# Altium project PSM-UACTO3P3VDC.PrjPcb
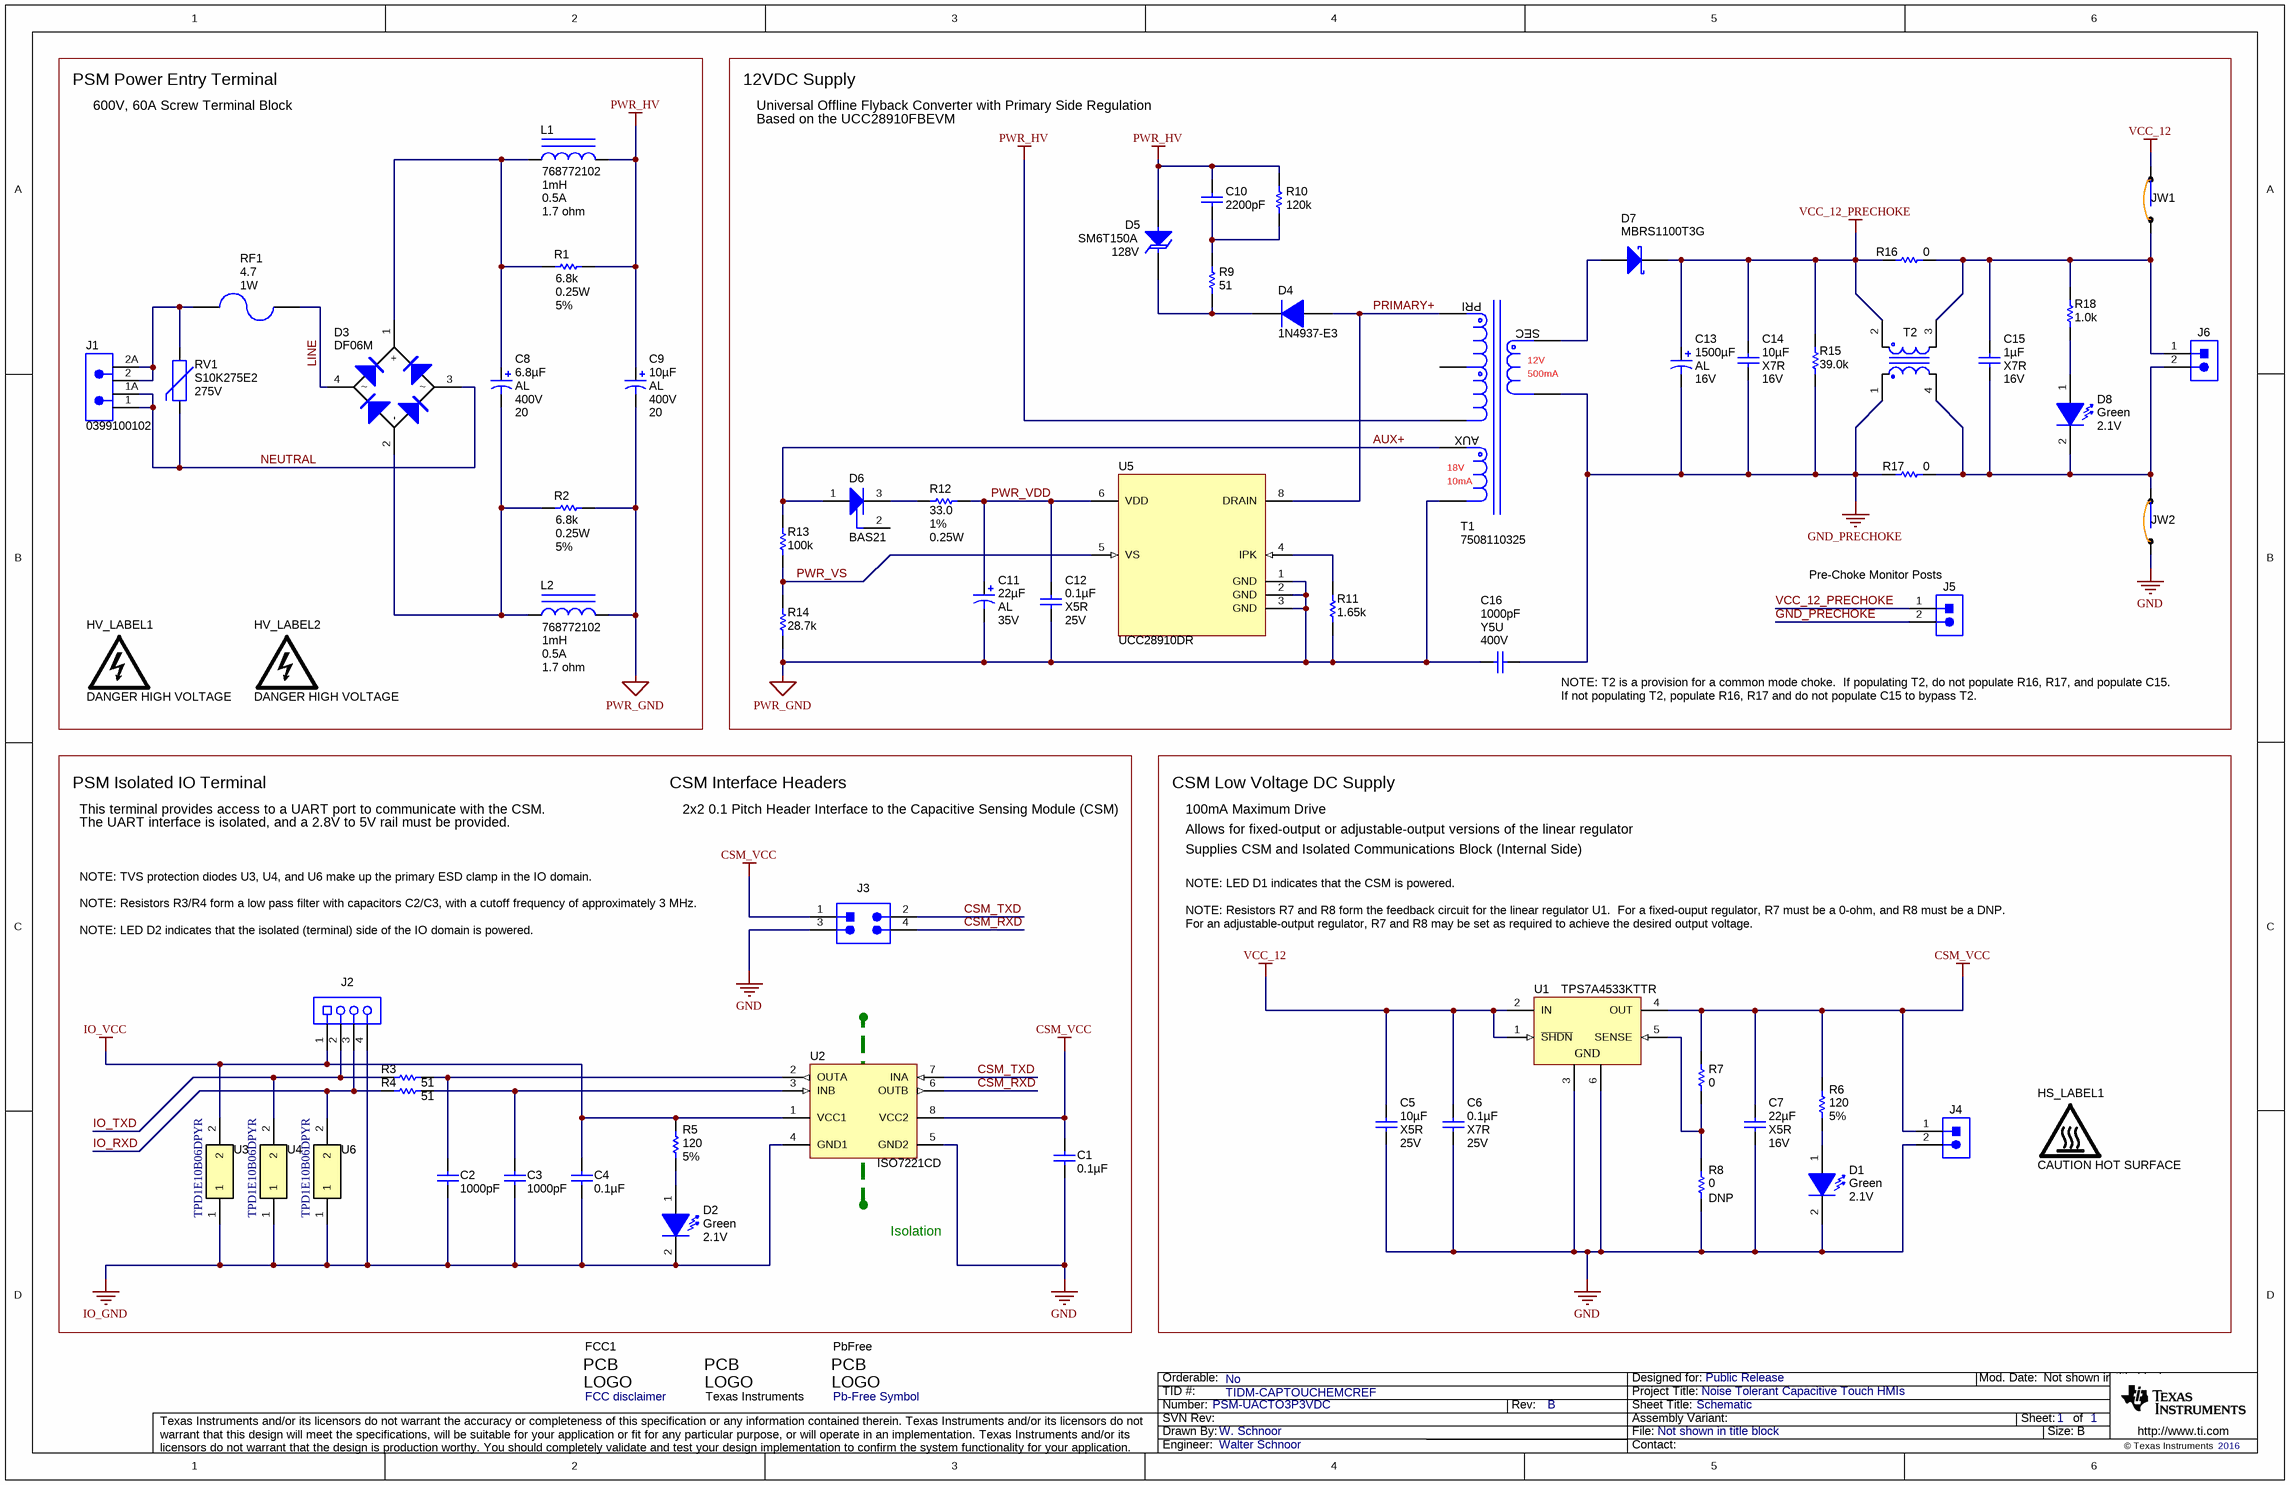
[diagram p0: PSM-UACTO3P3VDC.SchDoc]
CopyrightYear: 2016; EVM_Orderable: No; PCB_Layout: Walter Schnoor; PCB_Rev: B; PRJ_Customer: Public Release; PRJ_Engineer: Walter Schnoor; PRJ_Number: PSM-UACTO3P3VDC; PRJ_Title: Noise Tolerant Capacitive Touch HMIs; SCH_Rev: B; TID: TIDM-CAPTOUCHEMCREF
1 sheet, 68 parts. Net scope: global (net labels, ports and power ports of the same name join across sheets).
Board file: PSM-UACTO3P3VDC.PcbDoc

## Sheet PSM-UACTO3P3VDC.SchDoc: Schematic
size 431 x 279 mm; Date: Not shown in title block; ApprovedBy: Not shown in title block; CheckedBy: Not shown in title block; Author: Not shown in title block; CompanyName: Not shown in title block; DrawnBy: W. Schnoor; Engineer: Not shown in title block; Organization: Not shown in title block; Address1: Not shown in title block; Address2: Not shown in title block; Address3: Not shown in title block; Address4: Not shown in title block; DocumentNumber: 1; Revision: Use project parameter SCH_Rev; SheetNumber: 1; SheetTotal: 1; PageSetup: Record=PageOptions¦CenterHorizontal=True¦CenterVertical=True¦PrintScale=0.62¦XCorrection=1.00¦YCorrection=1.00¦PrintKind=0¦BorderSize=5000000¦LeftOffset=0¦BottomOffset=0¦Orientation=2¦PaperLength=2794¦PaperWidth=2159¦Scale=100¦PaperSource=15¦PrintQuality=600¦MediaType=1¦DitherType=10¦PrintScaleMode=1¦PaperKind=Letter (8.5 x 11")¦PaperIndex=1

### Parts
C1  ValueDisplayed: 0.1µF  [0603]  (hidden comment: GRM188R71C104KA01D)
C2  ValueDisplayed: 1000pF  [0603]  (hidden comment: 06031C102JAT2A)
C3  ValueDisplayed: 1000pF  [0603]  (hidden comment: 06031C102JAT2A)
C4  ValueDisplayed: 0.1µF  [0603]  (hidden comment: GRM188R71C104KA01D)
C5  ValueDisplayed: 10µF  Value2: 25V  TempCo: X5R  [0805_HV]  (hidden comment: C2012X5R1E106K125AB)
C6  ValueDisplayed: 0.1µF  Value2: 25V  TempCo: X7R  [0805_HV]  (hidden comment: 08053C104KAT2A)
C7  ValueDisplayed: 22µF  Value2: 16V  TempCo: X5R  [0805_HV]  (hidden comment: C2012X5R1C226K125AC)
C8  ValueDisplayed: 6.8µF  Tolerance_%: 20  Value2: 400V  Technology: AL  [CAPPR5-10x16]  (hidden comment: UCA2G6R8MPD1TD)
C9  ValueDisplayed: 10µF  Tolerance_%: 20  Value2: 400V  Technology: AL  [CAPPR5-10X20]  (hidden comment: EEUED2G100)
C10  ValueDisplayed: 2200pF  [1206]  (hidden comment: C3216C0G2J222J)
C11  ValueDisplayed: 22µF  Value2: 35V  Technology: AL  [M_500x1100]  (hidden comment: ECA-1VM220)
C12  ValueDisplayed: 0.1µF  Value2: 25V  TempCo: X5R  [0603]  (hidden comment: 06033D104KAT2A)
C13  ValueDisplayed: 1500µF  Value2: 16V  Technology: AL  [ZLJ_1000X2000]  (hidden comment: 16ZLJ1500M10X20)
C14  ValueDisplayed: 10µF  Value2: 16V  TempCo: X7R  [1206]  (hidden comment: C3216X7R1C106M)
C15  ValueDisplayed: 1µF  Value2: 16V  TempCo: X7R  [1206]  (hidden comment: C3216X7R1C105K/0.85)
C16  ValueDisplayed: 1000pF  Value2: 400V  TempCo: Y5U  [440L_930x1250]  (hidden comment: 440LD10-R)
D1  value Green  Value2: 2.1V  [HLMP-351_GREEN]  (hidden comment: HLMP-3519)
D2  value Green  Value2: 2.1V  [HLMP-351_GREEN]  (hidden comment: HLMP-3519)
D3  DF06M  [DIOB_DFM]
D4  1N4937-E3  [DO-41]
D5  SM6T150A  value 128V  [SMB]
D6  BAS21  [INF-SOT23_N]
D7  MBRS1100T3G  [SMB]
D8  value Green  Value2: 2.1V  [HLMP-351_GREEN]  (hidden comment: HLMP-3519)
FCC1  FCC disclaimer  [FCC_disclaimer]  (no BOM)
HS_LABEL1  CAUTION HOT SURFACE  [IEC_HotSurface_Small]  (no BOM)
HV_LABEL1  DANGER HIGH VOLTAGE  [IEC_HighVoltage_Medium]  (no BOM)
HV_LABEL2  DANGER HIGH VOLTAGE  [IEC_HighVoltage_Medium]  (no BOM)
J1  0399100102  [CONN_399100102]
J2  39544-3004  [MOLEX_39544-3004]  (value not drawn)
J3  PEC02DAAN  [Sullins_PEC02DAAN]  (value not drawn)
J4  HTSW-102-07-G-S  [Samtec_HTSW-102-07-G-S]  (value not drawn)
J5  HTSW-102-07-G-S  [Samtec_HTSW-102-07-G-S]  (value not drawn)
J6  HTSW-102-07-G-S  [Samtec_HTSW-102-07-G-S]  (value not drawn)
JW1  923345-03-C  [923345-03-C]  (value not drawn)
JW2  923345-03-C  [923345-03-C]  (value not drawn)
L1  768772102  value 1mH  Value1: 1.7 ohm  Value2: 0.5A  [IND_WE-TI_8095]
L2  768772102  value 1mH  Value1: 1.7 ohm  Value2: 0.5A  [IND_WE-TI_8095]
LOGO2  Texas Instruments  [TI_Horizontal_Overlay_Medium]  (no BOM)
PbFree  Pb-Free Symbol  [Pb-Free_Overlay_Medium]  (no BOM)
R1  ValueDisplayed: 6.8k  Value1: 5%  Value2: 0.25W  [1206]  (hidden comment: CRCW12066K80JNEA)
R2  ValueDisplayed: 6.8k  Value1: 5%  Value2: 0.25W  [1206]  (hidden comment: CRCW12066K80JNEA)
R3  ValueDisplayed: 51  [0603]  (hidden comment: CRCW060351R0JNEA)
R4  ValueDisplayed: 51  [0603]  (hidden comment: CRCW060351R0JNEA)
R5  ValueDisplayed: 120  Value1: 5%  [0603]  (hidden comment: CRCW0603120RJNEA)
R6  ValueDisplayed: 120  Value1: 5%  [0603]  (hidden comment: CRCW0603120RJNEA)
R7  value 0  [0805_HV]  (hidden comment: CRCW08050000Z0EA)
R8  value 0  [0805_HV]  (hidden comment: CRCW08050000Z0EA)
R9  ValueDisplayed: 51  [0805_HV]  (hidden comment: CRCW080551R0JNEA)
R10  ValueDisplayed: 120k  [1206]  (hidden comment: CRCW1206120KJNEA)
R11  ValueDisplayed: 1.65k  [1206]  (hidden comment: CRCW12061K65FKEA)
R12  ValueDisplayed: 33.0  Value1: 1%  Value2: 0.25W  [1206]  (hidden comment: ERJ-8ENF33R0V)
R13  ValueDisplayed: 100k  [1206]  (hidden comment: CRCW1206100KFKEA)
R14  ValueDisplayed: 28.7k  [1206]  (hidden comment: CRCW120628K7FKEA)
R15  ValueDisplayed: 39.0k  [1206]  (hidden comment: RC1206FR-0739KL)
R16  ValueDisplayed: 0  [1206]  (hidden comment: CRCW12060000Z0EA)
R17  ValueDisplayed: 0  [1206]  (hidden comment: CRCW12060000Z0EA)
R18  ValueDisplayed: 1.0k  [1206]  (hidden comment: CRCW12061K00JNEA)
RF1  ValueDisplayed: 4.7  Value2: 1W  [RESAD1524W55L900D150]  (hidden comment: FKN1WSJR-52-4R7)
RV1  value 275V  [VAR_S10K275E2]  (hidden comment: S10K275E2)
T1  7508110325  [7508110325]
T2  SRF0905-472Y  [SRF0905]  (value not drawn)
U1  TPS7A4533KTTR  [KTT0005A_N]
U2  ISO7221CD  [D0008A_N]
U3  TPD1E10B06DPYR  [DPY0002A]
U4  TPD1E10B06DPYR  [DPY0002A]
U5  UCC28910DR  [D0007A_N]
U6  TPD1E10B06DPYR  [DPY0002A]

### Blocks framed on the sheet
PSM Power Entry Terminal: C8 C9 D3 HV_LABEL1 HV_LABEL2 J1 L1 L2 R1 R2 RF1 RV1
12VDC Supply: C10-C16 D4-D8 J5 J6 JW1 JW2 R9-R18 T1 T2 U5
CSM Low Voltage DC Supply: C5-C7 D1 HS_LABEL1 J4 R6-R8 U1

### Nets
CSM_VCC: C1.1 C7.1 J3.1 J4.1 R6.2 R7.2 U1.4(OUT) U2.8(VCC2)
GND: C1.2 C5.2 C6.2 C7.2 D1.2(K) J3.3 J4.2 JW2.1 R8.1 U1.3(GND) U1.6(GND) U2.5(GND2)
GND_PRECHOKE: C13.2(-) C14.2 C16.2 J5.2 R15.1 R17.1 T1.8 T2.1
IO_GND: C2.2 C3.2 C4.2 D2.2(K) J2.4 U2.4(GND1) U3.1 U4.1 U6.1
IO_VCC: C4.1 J2.1 R5.2 U2.1(VCC1) U3.2
PWR_GND: C9.2(-) C11.2(-) C12.2 C16.1 L2.2 R2.2 R11.1 R14.1 T1.4 U5.1(GND) U5.2(GND) U5.3(GND)
PWR_HV: C9.1(+) C10.1 D5.2(A) L1.2 R1.2 R10.2 T1.1
VCC_12: C5.1 C6.1 JW1.2 U1.1(~{SHDN}) U1.2(IN)
VCC_12_PRECHOKE: C13.1(+) C14.1 D7.1(K) J5.1 R15.2 R16.1 T2.2
AUX+: D6.1(A) R13.1 T1.5
CSM_RXD: J3.4 U2.6(OUTB)
CSM_TXD: J3.2 U2.7(INA)
IO_RXD: J2.3 R4.1 U6.2
IO_TXD: J2.2 R3.1 U4.2
LINE: D3.4 RF1.1
NEUTRAL: D3.3 J1.1 J1.1A RV1.2
PRIMARY+: D4.2(A) T1.3 U5.8(DRAIN)
PWR_VDD: C11.1(+) C12.1 R12.1 U5.6(VDD)
PWR_VS: R13.2 R14.2 U5.5(VS)
NetC2_1: C2.1 R3.2 U2.2(OUTA)
NetC3_1: C3.1 R4.2 U2.3(INB)
NetC8_1: C8.1(+) D3.1(+) L1.1 R1.1
NetC8_2: C8.2(-) D3.2(-) L2.1 R2.1
NetC10_2: C10.2 R9.2 R10.1
NetC15_1: C15.1 J6.1 JW1.1 R16.2 R18.2 T2.3
NetC15_2: C15.2 D8.2(K) J6.2 JW2.2 R17.2 T2.4
NetD1_1: D1.1(A) R6.1
NetD2_1: D2.1(A) R5.1
NetD4_1: D4.1(K) D5.1(K) R9.1
NetD6_3: D6.3(K) R12.2
NetD7_2: D7.2(A) T1.7
NetD8_1: D8.1(A) R18.1
NetJ1_2: J1.2 J1.2A RF1.2 RV1.1
NetR7_1: R7.1 R8.2 U1.5(SENSE)
NetR11_2: R11.2 U5.4(IPK)

Not connected (* = marked no-connect by the designer): D6 2(NC); T1 2

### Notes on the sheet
- 600V, 60A Screw Terminal Block
- Universal Offline Flyback Converter with Primary Side Regulation
- Based on the UCC28910FBEVM
- (near J5) Pre-Choke Monitor Posts
- NOTE: T2 is a provision for a common mode choke.  If populating T2, do not populate R16, R17, and populate C15.
- If not populating T2, populate R16, R17 and do not populate C15 to bypass T2.
- PSM Isolated IO Terminal
- This terminal provides access to a UART port to communicate with the CSM.
- The UART interface is isolated, and a 2.8V to 5V rail must be provided.
- CSM Interface Headers
- 2x2 0.1 Pitch Header Interface to the Capacitive Sensing Module (CSM)
- 100mA Maximum Drive
- Allows for fixed-output or adjustable-output versions of the linear regulator
- NOTE: TVS protection diodes U3, U4, and U6 make up the primary ESD clamp in the IO domain.
- NOTE: Resistors R3/R4 form a low pass filter with capacitors C2/C3, with a cutoff frequency of approximately 3 MHz.
- Supplies CSM and Isolated Communications Block (Internal Side)
- NOTE: LED D1 indicates that the CSM is powered.
- NOTE: LED D2 indicates that the isolated (terminal) side of the IO domain is powered.
- NOTE: Resistors R7 and R8 form the feedback circuit for the linear regulator U1.  For a fixed-ouput regulator, R7 must be a 0-ohm, and R8 must be a DNP.
- For an adjustable-output regulator, R7 and R8 may be set as required to achieve the desired output voltage.
- Isolation
- (near R8) DNP

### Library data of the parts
C1 C4 = GRM188R71C104KA01D: CAP, CERM, 0.1 µF, 16 V, +/- 10%, X7R, 0603; Manufacturer: MuRata; Polarized: N; CompType: Capacitor; Value: 0.1uF; U/M: EA; Cap_F: 0.0000001; Tolerance_%: 10; Value1: Unknown; VDC_V: 16; Value2: 16V; TaMin_C: -55; TaMax_C: 125
C2 C3 = 06031C102JAT2A: CAP, CERM, 1000 pF, 100 V, +/- 5%, X7R, 0603; Manufacturer: AVX; Polarized: N; CompType: Capacitor; Value: 1000pF; U/M: EA; Cap_F: 0.000000001; Tolerance_%: 5; ESR_ohm: 0.276; Value1: 0.276 ohm; VDC_V: 100; Value2: 100V; TaMin_C: -55; TaMax_C: 125
C5 = C2012X5R1E106K125AB: CAP, CERM, 10 µF, 25 V, +/- 10%, X5R, 0805; Manufacturer: TDK; Polarized: N; CompType: Capacitor; Value: 10uF; U/M: EA; Cap_F: 0.00001; Tolerance_%: 10; Value1: Unknown; VDC_V: 25; TaMin_C: -55; TaMax_C: 85; Cap_Case: 0805
C6 = 08053C104KAT2A: CAP, CERM, 0.1 µF, 25 V, +/- 10%, X7R, 0805; Manufacturer: AVX; Polarized: N; CompType: Capacitor; Value: 0.1uF; U/M: EA; Cap_F: 0.0000001; Tolerance_%: 10; ESR_ohm: 0.28; Value1: 0.28 ohm; VDC_V: 25; TaMin_C: -55; TaMax_C: 125; Cap_Case: 0805
C7 = C2012X5R1C226K125AC: CAP, CERM, 22 µF, 16 V, +/- 10%, X5R, 0805; Manufacturer: TDK; Polarized: N; CompType: Capacitor; Value: 22uF; U/M: EA; Cap_F: 0.000022; Tolerance_%: 10; Value1: Unknown; VDC_V: 16; TaMin_C: -55; TaMax_C: 85; Cap_Case: 0805
C8 = UCA2G6R8MPD1TD: CAP, AL, 6.8 µF, 400 V, +/- 20%, TH; Manufacturer: Nichicon; Polarized: Y; CompType: Capacitor; Value: 6.8uF; U/M: EA; Cap_F: 0.0000068; Value1: Unknown; VDC_V: 400; TaMin_C: -25; TaMax_C: 105; Cap_Case: 10x16
C9 = EEUED2G100: CAP, AL, 10 µF, 400 V, +/- 20%, 2.864788 ohm, TH; Manufacturer: Panasonic; Polarized: Y; CompType: Capacitor; Value: 10uF; U/M: EA; Cap_F: 0.00001; VDC_V: 400; IRMS_A: 0.3; TaMin_C: -25; TaMax_C: 105
C10 = C3216C0G2J222J: CAP, CERM, 2200 pF, 630 V, +/- 5%, C0G/NP0, 1206; Manufacturer: TDK; Polarized: N; CompType: Capacitor; Value: 2200pF; U/M: EA; Cap_F: 0.0000000022; Tolerance_%: 5; ESR_ohm: 0.049; Value1: 0.049 ohm; VDC_V: 630; Value2: 630V; TaMin_C: -55; TaMax_C: 125
C11 = ECA-1VM220: CAP, AL, 22 µF, 35 V, +/- 20%, TH; Manufacturer: Panasonic; Polarized: Y; CompType: Capacitor; Value: 22uF; U/M: EA; Cap_F: 0.000022; Tolerance_%: 20; Value1: Unknown; VDC_V: 35; IRMS_A: 0.095; TaMin_C: -40; TaMax_C: 85; Cap_Case: 5x11
C12 = 06033D104KAT2A: CAP, CERM, 0.1 µF, 25 V, +/- 10%, X5R, 0603; Manufacturer: AVX; Polarized: N; CompType: Capacitor; Value: 0.1uF; U/M: EA; Cap_F: 0.0000001; Tolerance_%: 10; ESR_ohm: 0.048; Value1: 0.048 ohm; VDC_V: 25; IRMS_A: 0.53; TaMin_C: -55; TaMax_C: 85
C13 = 16ZLJ1500M10X20: CAP, AL, 1500 µF, 16 V, +/- 20%, 0.028 ohm, TH; Manufacturer: Rubycon; Polarized: Y; CompType: Capacitor; Value: 1500uF; U/M: EA; Cap_F: 0.0015; Tolerance_%: 20; VDC_V: 16; ESR_ohm: 0.028; IRMS_A: 2.5; TaMin_C: -40; TaMax_C: 105; Cap_Case: 10x20
C14 = C3216X7R1C106M: CAP, CERM, 10 µF, 16 V, +/- 20%, X7R, 1206; Manufacturer: TDK; Polarized: N; CompType: Capacitor; Value: 10uF; U/M: EA; Cap_F: 0.00001; Tolerance_%: 20; ESR_ohm: 0.0046; Value1: 0.0046 ohm; VDC_V: 16; TaMin_C: -55; TaMax_C: 125
C15 = C3216X7R1C105K/0.85: CAP, CERM, 1 µF, 16 V, +/- 10%, X7R, 1206; Manufacturer: TDK; Polarized: N; CompType: Capacitor; Value: 1uF; U/M: EA; Cap_F: 0.000001; Tolerance_%: 10; ESR_ohm: 0.01; Value1: 0.01 ohm; VDC_V: 16; TaMin_C: -55; TaMax_C: 125
C16 = 440LD10-R: CAP, CERM, 1000 pF, 400 V, +/- 20%, Y5U, Disc, 9.3x12.5mm; Manufacturer: Yageo America; Polarized: N; CompType: Capacitor; Value: 1000pF; U/M: EA; Cap_F: 0.000000001; Tolerance_%: 20; Value1: Unknown; VDC_V: 400; TaMin_C: -30; TaMax_C: 125
D1 D2 D8 = HLMP-3519: LED, Green, TH; Manufacturer: Avago; Vf_V: 2.1; Io_A: 0.01; Tjmax_C: 110; Value1: W; U/M: EA
D3 = DF06M: Diode, Switching-Bridge, 600 V, 1 A, TH; Manufacturer: Diodes Inc.; U/M: EA; Vf_V: 1.1; Value: 600V; Value1: 1A; Value2: 1.1V; Io_A: 1; Vr_V: 600; TJmax_C: 150
D4 = 1N4937-E3: Diode, Switching, 600 V, 1 A, TH; Manufacturer: Vishay-Semiconductor; U/M: EA; Vf_V: 1.2; Value: 600V; Value1: 1A; Value2: 1.2V; Io_A: 1; Vr_V: 600; TJmax_C: 150; RJC_CperW: 25
D5 = SM6T150A: Diode, TVS, Uni, 128 V, 600 W, SMB; Manufacturer: ST Microelectronics; U/M: EA; Power_W: 600; Vr_V: 128; Value1: 600W; RJA_CperW: 100
D6 = BAS21: Silicon Switching Diode, SOT23, Reel, Green; Manufacturer: Infineon; Configuration: Single; Green: TRUE; IF (max): 250 mA; IR (max): 100 nA; trr (max): 50 ns; VBR (min): 250 V; VF (max): 1.25 V; VR (max): 200 V
D7 = MBRS1100T3G: Diode, Schottky, 100 V, 1 A, SMB; Manufacturer: ON Semiconductor; U/M: EA; Vf_V: 0.75; Value: 100V; Value1: 1A; Value2: 0.75V; Io_A: 1; Vr_V: 100; TJmax_C: 150; RJC_CperW: 22
FCC1 = FCC_disclaimer: SymbolCreator: codlsc
HS_LABEL1 = IEC_HotSurface: IEC 61010-1 Hot Surface Warning; SymbolCreator: a0412235
HV_LABEL1 HV_LABEL2 = IEC_HighVoltage: IEC 61010-1 High Voltage Warning; SymbolCreator: a0412235
J1 = 0399100102: Terminal Block, 60A, 10.16mm Pitch, 2-Pos, TH; Manufacturer: Molex; SymbolCreator: a0799628; CompType: Connector; U/M: EA
J2 = 39544-3004: Terminal Block, 4x1, 5.08mm, TH; Manufacturer: Molex; SymbolCreator: a0411947; U/M: EA
J3 = PEC02DAAN: Header, 100mil, 2x2, Tin, TH; Manufacturer: Sullins Connector Solutions; SymbolCreator: a0412235; U/M: EA
J4-J6 = HTSW-102-07-G-S: Header, 100mil, 2x1, Gold, TH; Manufacturer: Samtec; SymbolCreator: a0412235; U/M: EA
JW1 JW2 = 923345-03-C: Jumper Wire, 300mil spacing, Orange, pkg of 200; Manufacturer: 3M; SymbolCreator: a0412235; U/M: EA
L1 L2 = 768772102: Inductor, Shielded Drum Core, Metal Composite, 1 mH, 0.5 A, 1.7 ohm, TH; Manufacturer: Wurth Elektronik eiSos; Ind_H: 1.0E-3; Imax_A: 0.5; Irms: 0.5A @ 40C rise; Isat: 0.55A @ 10% inductance drop; DCR_ohm: 1.7
LOGO2 = TI_Logo: Texas Instrument Corporate Signature; SymbolCreator: a0412235
PbFree = Pb-Free: SymbolCreator: a0412235
R1 R2 = CRCW12066K80JNEA: RES, 6.8 k, 5%, 0.25 W, 1206; Manufacturer: Vishay-Dale; CompType: Resistor; Value: 6.8k; Res_ohm: 6800; Value_Code: 6k80; Tolerance_%: 5; Power_W: 0.25; VDC_V: 200; TempCo: 200 ppm/C; EIA_Code: E24; U/M: EA
R3 R4 = CRCW060351R0JNEA: RES, 51, 5%, 0.1 W, 0603; Manufacturer: Vishay-Dale; CompType: Resistor; Value: 51; Value_Code: 51R0; Tolerance_%: 5; Power_W: 0.1; Value2: 0.1W; VDC_V: 75; TempCo: 200 ppm/C; EIA_Code: E24; U/M: EA
R5 R6 = CRCW0603120RJNEA: RES, 120, 5%, 0.1 W, 0603; Manufacturer: Vishay-Dale; CompType: Resistor; Value: 120; Value_Code: 120R; Tolerance_%: 5; Power_W: 0.1; Value2: 0.1W; VDC_V: 75; TempCo: 200 ppm/C; EIA_Code: E24; U/M: EA
R7 R8 = CRCW08050000Z0EA: RES, 0 ohm, 5%, 0.125W, 0805; Manufacturer: Vishay-Dale; CompType: Resistor; Value_Code: 0000; Tolerance_%: 5; Power_W: 0.125; VDC_V: 150; TempCo: 200 ppm/C; EIA_Code: E24; U/M: EA
R9 = CRCW080551R0JNEA: RES, 51, 5%, 0.125 W, 0805; Manufacturer: Vishay-Dale; CompType: Resistor; Value: 51; Value_Code: 51R0; Tolerance_%: 5; Power_W: 0.125; Value2: 0.125W; VDC_V: 150; TempCo: 200 ppm/C; EIA_Code: E24; U/M: EA
R10 = CRCW1206120KJNEA: RES, 120 k, 5%, 0.25 W, 1206; Manufacturer: Vishay-Dale; CompType: Resistor; Value: 120k; Res_ohm: 120000; Tolerance_%: 5; Power_W: 0.25; Value2: 0.25W; VDC_V: 200; TempCo: 200 ppm/C; EIA_Code: E24; U/M: EA
R11 = CRCW12061K65FKEA: RES, 1.65 k, 1%, 0.25 W, 1206; Manufacturer: Vishay-Dale; CompType: Resistor; Value: 1.65k; Res_ohm: 1650; Value_Code: 1k65; Tolerance_%: 1; Power_W: 0.25; Value2: 0.25W; VDC_V: 200; TempCo: 100 ppm/C; EIA_Code: E96; U/M: EA
R12 = ERJ-8ENF33R0V: RES, 33.0, 1%, 0.25 W, 1206; Manufacturer: Panasonic; CompType: Resistor; Value: 33.0; Res_ohm: 33; Value_Code: 33R0; Tolerance_%: 1; Power_W: 0.25; VDC_V: 200; TempCo: 100 ppm/C; U/M: EA
R13 = CRCW1206100KFKEA: RES, 100 k, 1%, 0.25 W, 1206; Manufacturer: Vishay-Dale; CompType: Resistor; Value: 100k; Res_ohm: 100000; Tolerance_%: 1; Power_W: 0.25; Value2: 0.25W; VDC_V: 200; TempCo: 100 ppm/C; EIA_Code: E96; U/M: EA
R14 = CRCW120628K7FKEA: RES, 28.7 k, 1%, 0.25 W, 1206; Manufacturer: Vishay-Dale; CompType: Resistor; Value: 28.7k; Res_ohm: 28700; Value_Code: 28k7; Tolerance_%: 1; Power_W: 0.25; Value2: 0.25W; VDC_V: 200; TempCo: 100 ppm/C; EIA_Code: E96; U/M: EA; AEC Category: Q200
R15 = RC1206FR-0739KL: RES, 39.0 k, 1%, 0.25 W, 1206; Manufacturer: Yageo America; CompType: Resistor; Value: 39.0k; Res_ohm: 39000; Value_Code: 39k0; Tolerance_%: 1; Power_W: 0.25; Value2: 0.25W; VDC_V: 200; TempCo: 100 ppm/C; U/M: EA
R16 R17 = CRCW12060000Z0EA: RES, 0, 5%, 0.25 W, 1206; Manufacturer: Vishay-Dale; CompType: Resistor; Value: 0; Value_Code: 0000; Tolerance_%: 5; Power_W: 0.25; Value2: 0.25W; VDC_V: 200; TempCo: 200 ppm/C; EIA_Code: E24; U/M: EA
R18 = CRCW12061K00JNEA: RES, 1.0 k, 5%, 0.25 W, 1206; Manufacturer: Vishay-Dale; CompType: Resistor; Value: 1.0k; Res_ohm: 1000; Value_Code: 1k00; Tolerance_%: 5; Power_W: 0.25; Value2: 0.25W; VDC_V: 200; TempCo: 200 ppm/C; EIA_Code: E24; U/M: EA
RF1 = FKN1WSJR-52-4R7: RES, 4.7, 5%, 1 W, Fusible, TH; Manufacturer: Yageo America; SymbolCreator: a0412235; CompType: Fusible Resistor; Value: 4.7; Value_Code: 4R70; Tolerance_%: 5; Power_W: 1; TempCo: 350 ppm/C; EIA_Code: E24; U/M: EA
RV1 = S10K275E2: Varistor 275V RMS 10MM Radial, TH; Manufacturer: EPCOS Inc; SymbolCreator: a0412235
T1 = 7508110325: Flyback Transformer, 90-375V @ 100kHz (PRI), 12V/500mA (SEC), 18V/10mA (AUX); Manufacturer: Wurth Elektronik; SymbolCreator: a0273983; U/M: EA, IN, or GM
T2 = SRF0905-472Y: Line Filter; Manufacturer: Bourns; Alternate Manufacturer: None; CompType: Transformer; DCR_Ohm: 0.9; VDC_V: 50; Value: 4700 uH; LeakageL: 0.36; Imax_A: 0.4; Ind_H: 4.7E-3; U/M: EA
U1 = TPS7A4533KTTR: Single Output Fast Transient Response LDO, 1.5 A, Fixed 3.3 V Output, 2.1 to 20 V Input, 5-pin DDPAK (KTT), -40 to 125 degC, Green (RoHS & no Sb/Br); Manufacturer: Texas Instruments; Alternate Manufacturer: None; Alternate PartNumber: Equivalent; Accuracy(%): 1; Fixed Output Options(V): 3.3; Iout(Max)(A): 1.5; SubFamily: Single Channel LDO; Vdo(Typ)(mV): 300; Vin(Max)(V): 20; Vin(Min)(V): 2.1
U2 = ISO7221CD: 25 Mbps Dual Channels, 1 / 1, Digital Isolator, 3.3 V / 5 V, -40 to +125 degC, 8-pin SOIC (D), Green (RoHS & no Sb/Br); Manufacturer: Texas Instruments; Alternate Manufacturer: None; Alternate PartNumber: Equivalent; Datarate(Mbps): 25; Input Noise Filter: Yes; Insulation Rating(VRMS): 2500; Prop Delay(Max)(ns): 42; Rating: Catalog; Supply Voltage(s)(V): 3.3, 5; TTL/CMOS Input Threshold: TTL
U3 U4 U6 = TPD1E10B06DPYR: ESD in 0402 Package with 10 pF Capacitance and 6 V Breakdown, 1 Channel, -40 to +125 degC, 2-pin X2SON (DPY), Green (RoHS & no Sb/Br); Manufacturer: Texas Instruments; Alternate PartNumber: Equivalent; Breakdown Voltage(Min)(V): 6; Eco-Plan: TBD; IEC 61000-4-2 Air-Gap(+/- kV): 30; IO Capacitance(Typ)(pF): 10; SubFamily: ESD Solution
U5 = UCC28910DR: High-Voltage Flyback Switcher with Primary-Side Regulation and Constant-Current Control, D0007A; Manufacturer: Texas Instruments; SymbolCreator: a0412235; CompType: IC; U/M: EA

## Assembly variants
With Choke: not fitted R8 R16 R17
Without Choke: not fitted R8 T2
